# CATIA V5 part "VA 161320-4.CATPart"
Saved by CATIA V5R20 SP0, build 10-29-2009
Part number: VA 161320-4
Revision: ANY
Definition: UNKNOWN
Nomenclature: VA 161320-4
Source: Unknown
Bounding box of the stored display mesh (mm): x -5.5 to 5.5, y 0 to 5.5, z -5 to 5
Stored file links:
  C:\Users\Utente\Desktop\IO LAVORO\3D X SITO CF\CUMSA\3D files VA\VA 161320\VA 161320-4.CATPart
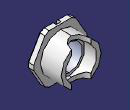
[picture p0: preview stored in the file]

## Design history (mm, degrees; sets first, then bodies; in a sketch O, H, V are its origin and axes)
Body1 "Cortar-Extruir4" (main body)
  Solid1: solid without history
